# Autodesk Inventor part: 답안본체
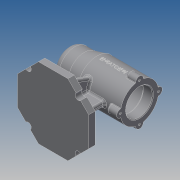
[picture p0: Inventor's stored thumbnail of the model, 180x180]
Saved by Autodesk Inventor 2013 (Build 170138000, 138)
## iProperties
Created: 2019-12
Part Number: 답안본체
Material: 일반
Document SubType Name: Modeling
Designer: Administrator
Density: 1 g/cm^3
Author: Administrator
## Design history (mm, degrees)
sketch "스케치1"
  geometry: L1 (0, 0)-(112, 0); L2 (112, 0)-(112, 30); L3 (112, 30)-(45, 30); L4 (45, 30)-(25, 25); L5 (25, 25)-(0, 25); L6 (0, 25)-(0, 0)
  constraints: 12 end point, 2 parallel, 2 perpendicular, 1 horizontal
  dimensions: "d0" = 112 distance of L1.start L1.end; "d2" = 60 diameter of L3 L1; "d3" = 50 diameter of L5 L1; "d4" = 25 distance of L4.end L5.end; "d5" = 45 horizontal distance of L5.end L3.end
revolve "회전1" sketch "스케치1" stored, may be unused: angle "d6" = 90 deg
node "작업 평면1"
sketch "스케치2"
  geometry: L1 (-112, 30)-(-112, -30) reference; L2 (0, 25)-(0, -25) reference; L3 (0, -56)-(-112, -56); L4 (-112, -56)-(-112, 56); L5 (-112, 56)-(0, 56); L6 (0, 56)-(0, -56); 3 further points
  constraints: 8 end point, 2 midpoint, 2 parallel, 2 point on line, 1 coincident, 1 horizontal, 1 perpendicular
  dimensions: "d8" = 112 distance of L5.end L3.start
extrude "돌출1" join sketch "스케치2" distance "d10" = 10; taper "d11" = 0 deg
sketch "스케치3"
  geometry: L1 (0, -56)-(112, -56) reference; L2 (112, -56)-(112, 56) reference; L3 (112, 56)-(112, -56) reference; L4 (112, -56)-(0, -56) reference; L5 (0, -56)-(0, 56) reference; L6 (0, 56)-(112, 56) reference; L7 (56, 0)-(112, 56); L8 (95.598, 39.598)-(118.782, 16.414); L9 (118.782, 16.414)-(66.566, 68.63); L10 (66.566, 68.63)-(127.601, 68.63); L11 (127.601, 68.63)-(127.601, 16.414); L12 (127.601, 16.414)-(118.782, 16.414); C1 r 5 at (95.598, 39.598); 3 further points
  constraints: 12 end point, 2 midpoint, 2 parallel, 2 perpendicular, 1 centre point, 1 collinear, 1 horizontal alignment, 1 point on line, 1 vertical alignment, 4 other
  dimensions: "d12" = 10 diameter of C1
extrude "돌출2" cut sketch "스케치3" distance "d13" = 10; taper "d14" = 0 deg
sketch "스케치4"
  geometry: L1 (112, 23.196)-(79.196, 56) reference; C1 r 5 at (95.598, 39.598); 1 further point
  constraints: 1 centre point, 1 midpoint
  dimensions: "d15" = 10 diameter of C1
extrude "돌출3" cut sketch "스케치4" distance "d16" = 10; taper "d17" = 0 deg
node "작업 평면2"
node "작업 평면3"
sketch "스케치5"
  geometry: L1 (-79.196, 10)-(32.804, 10) reference; L2 (32.804, 10)-(32.804, 0) reference; L3 (32.804, 0)-(-79.196, 0) reference; L4 (-79.196, 0)-(-79.196, 10) reference; L5 (-59.196, 10)-(-42.174, 56.766); L6 (-42.174, 56.766)-(-23.196, 56.766); L7 (-23.196, 56.766)-(-23.196, 10); L8 (-59.196, 10)-(-23.196, 10); 2 further points
  constraints: 8 end point, 1 midpoint, 1 parallel, 1 perpendicular, 1 point on line, 2 other
  dimensions: "d19" = 20 distance of L5.start L1.start; "d20" = 110 deg angle of L5 L1
extrude "돌출4" join sketch "스케치5" stored distance "d21" = 8; taper "d22" = 0 deg
node "작업 평면4"
sketch "스케치6"
  geometry: L1 (-79.196, 55)-(-79.196, 105) reference; L2 (-79.196, 105)-(-54.196, 105) reference; L3 (-54.196, 105)-(-34.196, 110) reference; L4 (-34.196, 110)-(32.804, 110) reference; L5 (32.804, 110)-(32.804, 50) reference; L6 (32.804, 50)-(-19.196, 50) reference; L7 (-19.196, 50)-(-19.196, 10) reference; L8 (-19.196, 10)-(32.804, 10) reference; L9 (32.804, 10)-(32.804, 0) reference; L10 (32.804, 0)-(-79.196, 0) reference; L11 (-79.196, 0)-(-79.196, 10) reference; L12 (-79.196, 10)-(-27.196, 10) reference; L13 (-27.196, 10)-(-27.196, 50) reference; L14 (-27.196, 50)-(-34.196, 50) reference; L15 (-34.196, 50)-(-54.196, 55) reference; L16 (-54.196, 55)-(-79.196, 55) reference; L17 (-61.196, 10)-(-39.775, 55.937); L18 (7.804, 10)-(7.804, 61.764); L19 (-39.775, 55.937)-(7.804, 61.764); L20 (-61.196, 10)-(7.804, 10); 1 further point
  constraints: 8 end point, 2 point on line, 1 collinear, 1 perpendicular
  dimensions: "d24" = 115 deg angle of L17 L12; "d25" = 18 distance of L11.end L17.start; "d26" = 25 distance of L8.end L18.start
extrude "돌출5" join sketch "스케치6" stored distance "d27" = 8; taper "d28" = 0 deg
sketch "스케치7"
  geometry: L1 (0, -25)-(0, 25) reference; L2 (0, 25)-(25, 25) reference; L3 (25, 25)-(45, 30) reference; L4 (45, 30)-(112, 30) reference; L5 (112, 30)-(112, -30) reference; L6 (112, -30)-(87, -30) reference; L7 (87, -30)-(87, -70) reference; L8 (87, -70)-(112, -70) reference; L9 (112, -70)-(112, -80) reference; L10 (112, -80)-(0, -80) reference; L11 (0, -80)-(0, -70) reference; L12 (0, -70)-(18, -70) reference; L13 (18, -70)-(37.524, -28.131) reference; L14 (37.524, -28.131)-(25, -25) reference; L15 (25, -25)-(0, -25) reference; L16 (112, 0)-(6, 0); L17 (112, 0)-(112, 21); L18 (112, 21)-(97, 21); L19 (97, 21)-(97, 24); L20 (97, 24)-(43, 24); L21 (43, 24)-(43, 21); L22 (43, 21)-(31, 21); L23 (31, 21)-(31, 17.5); L24 (31, 17.5)-(13, 17.5); L25 (13, 17.5)-(13, 16); L26 (13, 16)-(9, 16); L27 (9, 16)-(9, 10.5); L28 (9, 10.5)-(6, 10.5); L29 (6, 10.5)-(6, 0); 1 further point
  constraints: 28 end point, 7 parallel, 6 perpendicular, 1 midpoint, 1 point on line
  dimensions: "d29" = 106 distance of L16.start L16.end; "d30" = 21 distance of L16.start L17.end; "d31" = 15 distance of L17.end L18.end; "d32" = 48 diameter of L20 L16; "d33" = 42 diameter of L22 L16; "d34" = 35 diameter of L24 L16; "d35" = 32 diameter of L26 L16; "d36" = 21 diameter of L28 L16; "d37" = 3 distance of L27.end L28.end; "d38" = 4 distance of L25.end L26.end; "d39" = 18 distance of L23.end L24.end; "d40" = 12 distance of L21.end L22.end
revolve "회전2" sketch "스케치7" stored, may be unused: angle "d41" = 90 deg
fillet "모깎기1" dims "d42" = 10
fillet "모깎기2" dims "d43" = 3
sketch "스케치8"
  geometry: C1 r 6 at (0, 30); 1 further point
  constraints: 1 centre point, 1 vertical alignment, 1 other
  dimensions: "d44" = 12 diameter of C1
extrude "돌출6" join sketch "스케치8" distance "d45" = 16; taper "d46" = 0 deg
fillet "모깎기3" dims "d47" = 3
fillet "모깎기4" dims "d48" = 1
sketch "스케치9"
  geometry: A1 r 6 centre (0, 0) between (5.998, 0.171) and (-5.998, 0.171) reference
hole "구멍1" sketch "스케치9" at (0, 0) diameter "d52" = 3.242; stored, may be unused: countersink angle "d56" = 90 deg, drill point angle "d58" = 118 deg; dims "d53" = 8, "d54" = 4, "d55" = 2, "d57" = 11
chamfer "모따기1" distance "d62" = 1; stored, may be unused: second distance "d63" = 2, angle "d64" = 45 deg
fillet "모깎기5" dims "d65" = 3
fillet "모깎기6" dims "d66" = 0.3
fillet "모깎기7" dims "d67" = 3
fillet "모깎기8" dims "d68" = 3
fillet "모깎기9" dims "d69" = 3
node "작업 평면5"
sketch "스케치10"
  geometry: L1 (112, 6.771)-(112, 29.226) reference; 2 further points
  constraints: 1 horizontal alignment, 1 other
  dimensions: "d71" = 41 distance from line of L1 point (71, 0)
feature "엠보싱1" sketch "스케치10" dims "d72" = 0.5, "d73" = 0
node "솔리드1"
mirror "대칭1"
mirror "대칭2"
mirror "대칭3"
pattern_circular "원형 패턴1" dims "d50" = 360 deg
pattern_circular "원형 패턴2" dims angle "d60" = 360 deg
node "절단 모서리 투영1"
node "절단 모서리 투영2"
node "절단 모서리 투영3"
node "절단 모서리 투영4"
other parameters: "d18" = -56, "d23" = -56, "d70" = 37
